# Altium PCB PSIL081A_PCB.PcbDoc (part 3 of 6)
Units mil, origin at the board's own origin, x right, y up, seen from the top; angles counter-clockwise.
Board outline 14000 x 8000 mil, 10 copper layers (Top Layer, Signal Layer 1, Signal Layer 2, Signal Layer 3, Signal Layer 4, Signal Layer 5, Signal Layer 6, Signal Layer 7, Signal Layer 8, Bottom Layer), stack 60.9 mil thick; 433 components, 510 nets, 1716 pads, 590 vias.
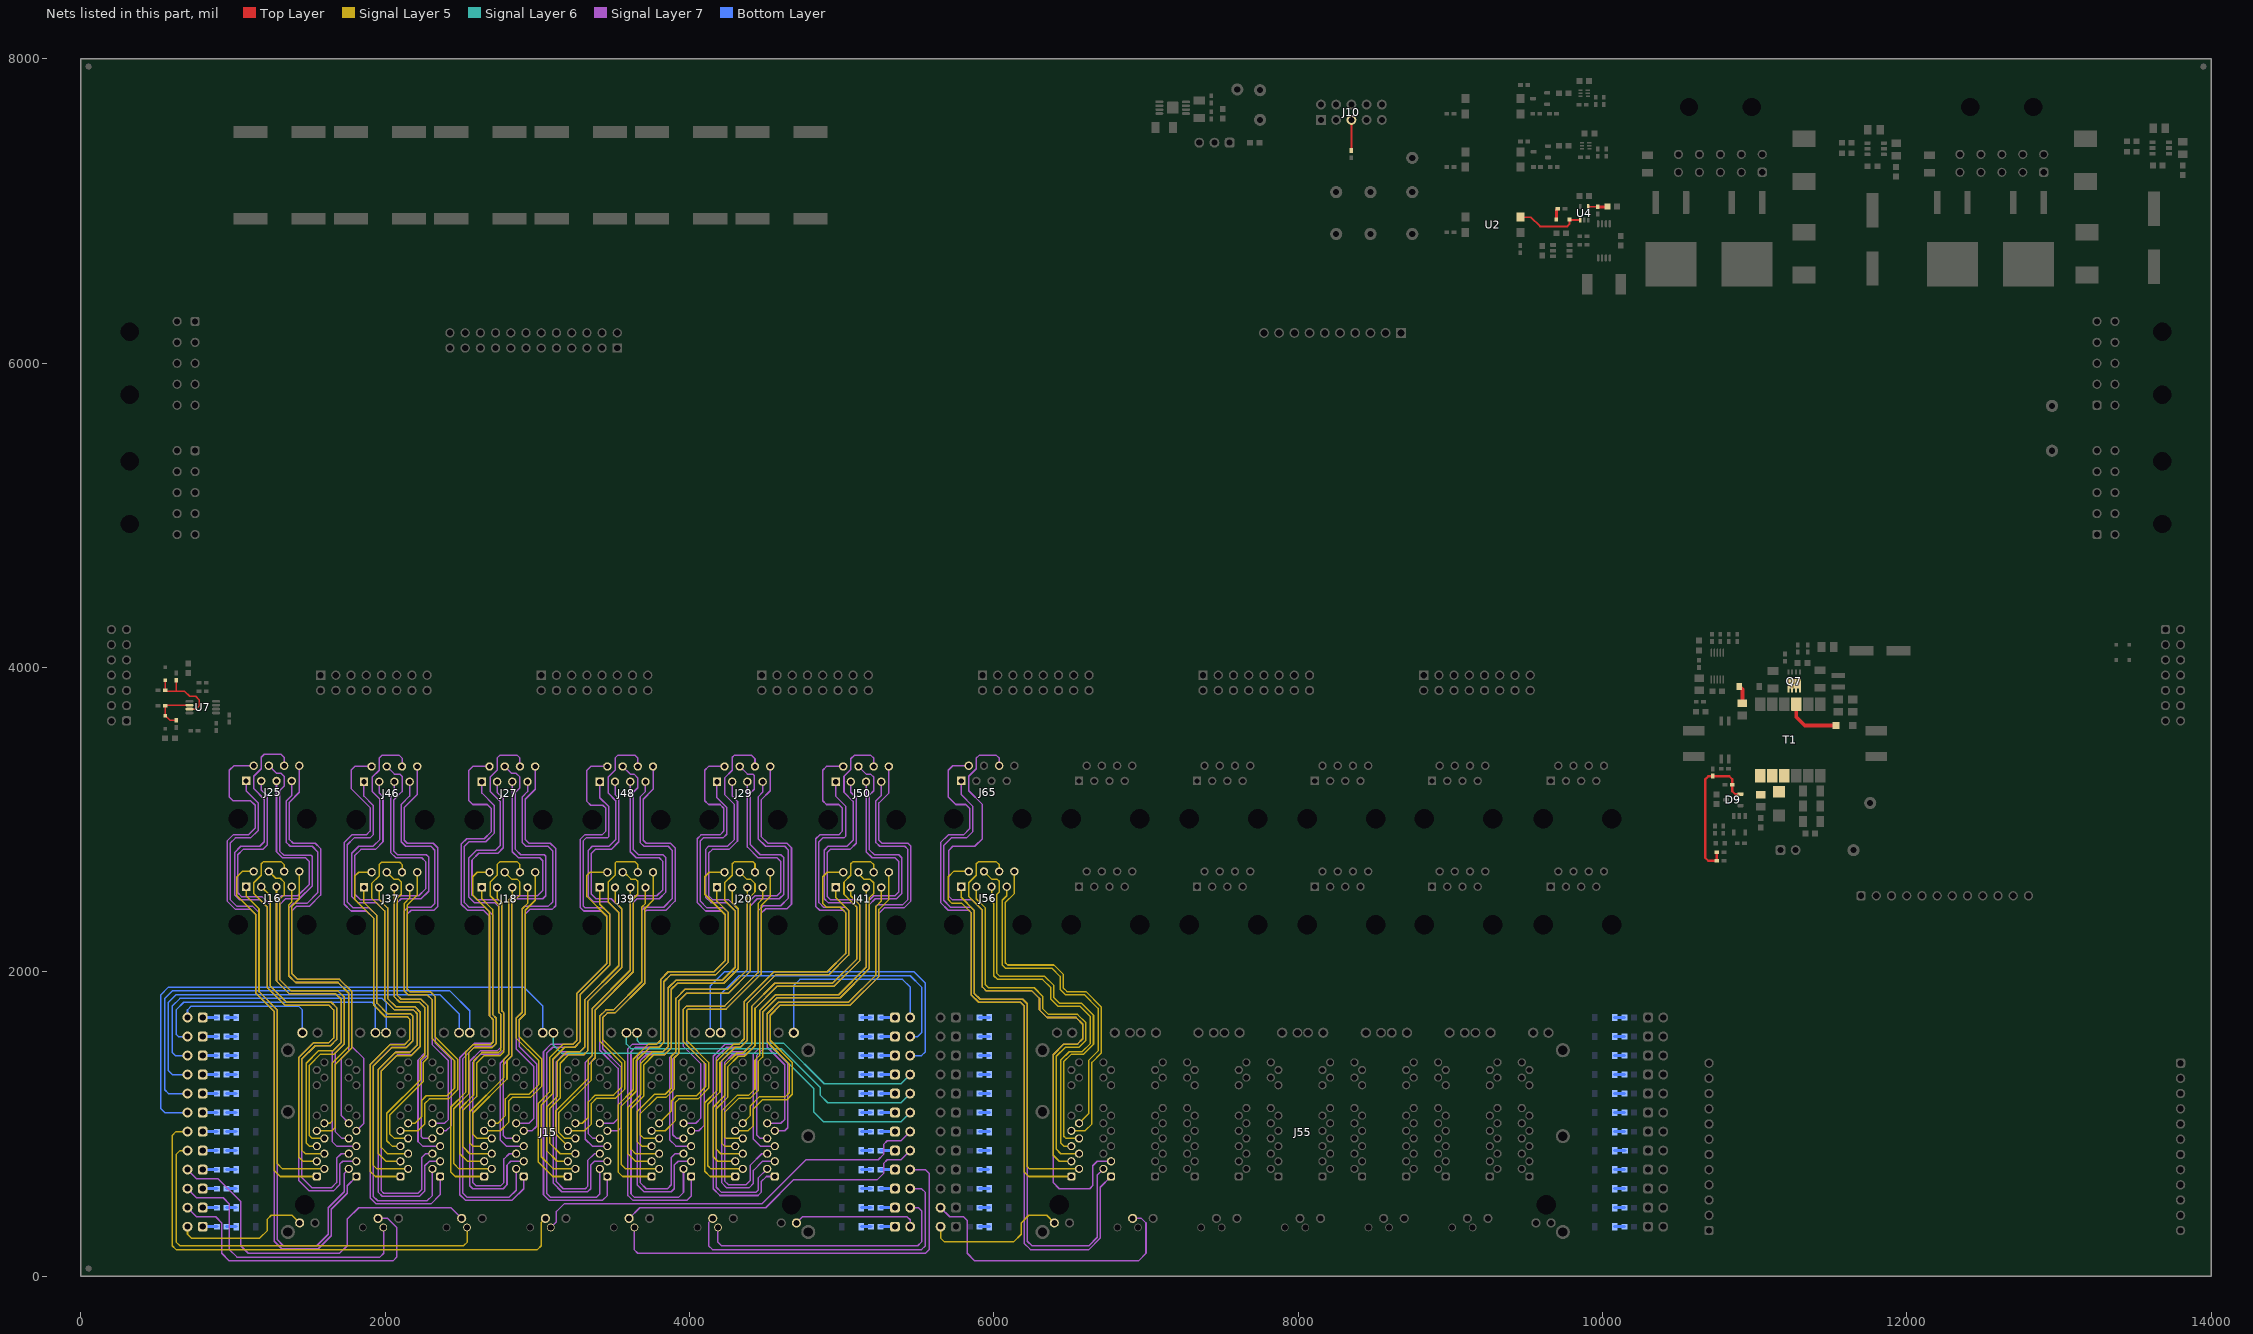
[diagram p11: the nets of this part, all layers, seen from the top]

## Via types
v1: diameter 34, hole 16, Top Layer to Bottom Layer, 429 vias
v2: diameter 26, hole 8, Top Layer to Bottom Layer, 156 vias
v3: diameter 19.68, hole 7.87, Top Layer to Bottom Layer, 5 vias

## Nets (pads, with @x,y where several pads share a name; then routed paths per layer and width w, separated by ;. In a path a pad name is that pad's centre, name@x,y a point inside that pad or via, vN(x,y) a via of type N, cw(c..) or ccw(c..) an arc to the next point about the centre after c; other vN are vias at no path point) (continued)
NetC58_2: C58.2 R18.2 U4.4 | length 128.8
  Top Layer w12: U4.4@9905.59,7029.29 9969.33,7029.29 R18.2@9970,7028.62
  Top Layer w20: R18.2@9970,7028.62 10032.13,7028.62 C58.2@10033.5,7030
NetD3_1: D3.1 U2.2 U4.1 | length 456.7
  Top Layer w12: U2.2@9461.59,6960 9530,6960 9590,6900 9770,6900 9783.31,6913.31 D3.1@9783.31,6945 9787.6,6940.71 U4.1@9854.41,6940.71
NetD3_2: D3.2 R5.2 | length 74
  Top Layer w20: D3.2@9696.69,6945 9696.69,7005.31 R5.2@9706.38,7015
NetD6_2: D6.2 R29.1 T1.7 T1.8 T1.9
NetD7_2: D7.2 Q7.5 Q7.6 Q7.7 Q7.8 Q7.9 T1.3 | length 359.7
  Top Layer w25: T1.3@11275,3759.61 T1.3@11274.37,3760.24 11274.37,3675.63 11330,3620 D7.2@11525.53,3620
NetD8_2: D8.2 R33.2 | length 118.1
  Top Layer w25: D8.2@10900.53,3875 10920,3855.53 R33.2@10920,3765
NetD9_2: D9.2 R39.1 R41.1 R42.1 R43.1 | length 991.9
  Top Layer w15: R43.1@10751.38,2785 R39.1@10751.38,2730 10695,2730 10675,2750 10675,3265 10696.38,3286.38 R41.1@10725,3286.38 10833.62,3286.38 10853.62,3266.38 R42.1@10853.62,3230 10853.62,3186.38 10872.6,3167.4 D9.2@10907.24,3167.4
NetD10_2: D10.2 R49.1 | length 64
  Bottom Layer w20: R49.1@955.96,325 D10.2@1020,325
NetD11_2: D11.2 R50.1 | length 64
  Bottom Layer w20: R50.1@955.96,825 D11.2@1020,825
NetD12_2: D12.2 R51.1 | length 64
  Bottom Layer w20: D12.2@5129.47,700 R51.1@5193.5,700
NetD13_2: D13.2 R52.2 | length 64
  Bottom Layer w20: R52.2@955.96,450 D13.2@1020,450
NetD14_2: D14.2 R53.2 | length 64
  Bottom Layer w20: R53.2@955.96,950 D14.2@1020,950
NetD15_2: D15.2 R54.2 | length 64
  Bottom Layer w20: D15.2@5129.47,575 R54.2@5193.5,575
NetD16_2: D16.2 R55.1 | length 64
  Bottom Layer w20: R55.1@955.96,1700 D16.2@1020,1700
NetD17_2: D17.2 R56.1 | length 64
  Bottom Layer w20: R56.1@955.96,1200 D17.2@1020,1200
NetD18_2: D18.2 R57.1 | length 64
  Bottom Layer w20: D18.2@5129.47,1325 R57.1@5193.5,1325
NetD19_2: D19.2 R58.2 | length 64
  Bottom Layer w20: R58.2@955.96,1575 D19.2@1020,1575
NetD20_2: D20.2 R59.2 | length 64
  Bottom Layer w20: R59.2@955.96,1075 D20.2@1020,1075
NetD21_2: D21.2 R60.2 | length 64
  Bottom Layer w20: D21.2@5129.47,1450 R60.2@5193.5,1450
NetD22_2: D22.2 R61.1 | length 64
  Bottom Layer w20: R61.1@955.96,575 D22.2@1020,575
NetD23_2: D23.2 R62.1 | length 64
  Bottom Layer w20: D23.2@5129.47,950 R62.1@5193.5,950
NetD24_2: D24.2 R63.1 | length 64
  Bottom Layer w20: D24.2@5129.47,450 R63.1@5193.5,450
NetD25_2: D25.2 R64.2 | length 64
  Bottom Layer w20: R64.2@955.96,700 D25.2@1020,700
NetD26_2: D26.2 R65.2 | length 64
  Bottom Layer w20: D26.2@5129.47,825 R65.2@5193.5,825
NetD27_2: D27.2 R66.2 | length 64
  Bottom Layer w20: D27.2@5129.47,325 R66.2@5193.5,325
NetD28_2: D28.2 R67.1 | length 64
  Bottom Layer w20: R67.1@955.96,1450 D28.2@1020,1450
NetD29_2: D29.2 R68.1 | length 64
  Bottom Layer w20: D29.2@5129.47,1075 R68.1@5193.5,1075
NetD30_2: D30.2 R69.1 | length 64
  Bottom Layer w20: D30.2@5129.47,1575 R69.1@5193.5,1575
NetD31_2: D31.2 R70.2 | length 64
  Bottom Layer w20: R70.2@955.96,1325 D31.2@1020,1325
NetD32_2: D32.2 R71.2 | length 64
  Bottom Layer w20: D32.2@5129.47,1200 R71.2@5193.5,1200
NetD33_2: D33.2 R72.2 | length 64
  Bottom Layer w20: D33.2@5129.47,1700 R72.2@5193.5,1700
NetD34_2: D34.2 R73.1 | length 64
  Bottom Layer w20: R73.1@5906.5,325 D34.2@5970.53,325
NetD35_2: D35.2 R74.1 | length 64
  Bottom Layer w20: R74.1@5906.5,825 D35.2@5970.53,825
NetD36_2: D36.2 R75.1 | length 64
  Bottom Layer w20: D36.2@10079.47,700 R75.1@10143.5,700
NetD37_2: D37.2 R76.2 | length 64
  Bottom Layer w20: R76.2@5906.5,450 D37.2@5970.53,450
NetD38_2: D38.2 R77.2 | length 64
  Bottom Layer w20: R77.2@5906.5,950 D38.2@5970.53,950
NetD39_2: D39.2 R78.2 | length 64
  Bottom Layer w20: D39.2@10079.47,575 R78.2@10143.5,575
NetD40_2: D40.2 R79.1 | length 64
  Bottom Layer w20: R79.1@5906.5,1700 D40.2@5970.53,1700
NetD41_2: D41.2 R80.1 | length 64
  Bottom Layer w20: R80.1@5906.5,1200 D41.2@5970.53,1200
NetD42_2: D42.2 R81.1 | length 64
  Bottom Layer w20: D42.2@10079.47,1325 R81.1@10143.5,1325
NetD43_2: D43.2 R82.2 | length 64
  Bottom Layer w20: R82.2@5906.5,1575 D43.2@5970.53,1575
NetD44_2: D44.2 R83.2 | length 64
  Bottom Layer w20: R83.2@5906.5,1075 D44.2@5970.53,1075
NetD45_2: D45.2 R84.2 | length 64
  Bottom Layer w20: D45.2@10079.47,1450 R84.2@10143.5,1450
NetD46_2: D46.2 R85.1 | length 64
  Bottom Layer w20: R85.1@5906.5,575 D46.2@5970.53,575
NetD47_2: D47.2 R86.1 | length 64
  Bottom Layer w20: D47.2@10079.47,950 R86.1@10143.5,950
NetD48_2: D48.2 R87.1 | length 64
  Bottom Layer w20: D48.2@10079.47,450 R87.1@10143.5,450
NetD49_2: D49.2 R88.2 | length 59
  Bottom Layer w20: R88.2@5906.5,700 D49.2@5965.53,700
NetD50_2: D50.2 R89.2 | length 69
  Bottom Layer w20: D50.2@10079.47,825 R89.2@10148.5,825
NetD51_2: D51.2 R90.2 | length 64
  Bottom Layer w20: D51.2@10079.47,325 R90.2@10143.5,325
NetD52_2: D52.2 R91.1 | length 64
  Bottom Layer w20: R91.1@5906.5,1450 D52.2@5970.53,1450
NetD53_2: D53.2 R92.1 | length 64
  Bottom Layer w20: D53.2@10079.47,1075 R92.1@10143.5,1075
NetD54_2: D54.2 R93.1 | length 64
  Bottom Layer w20: D54.2@10079.47,1575 R93.1@10143.5,1575
NetD55_2: D55.2 R94.2 | length 64
  Bottom Layer w20: R94.2@5906.5,1325 D55.2@5970.53,1325
NetD56_2: D56.2 R95.2 | length 64
  Bottom Layer w20: D56.2@10079.47,1200 R95.2@10143.5,1200
NetD57_2: D57.2 R96.2 | length 64
  Bottom Layer w20: D57.2@10079.47,1700 R96.2@10143.5,1700
NetD58_1: D58.1 R9.2 R17.2 U7.3 | length 501
  Top Layer w10: D58.1@555,3916.69 553.62,3915.32 R17.2@553.62,3850 558.62,3845 625,3845 ; R9.2@625,3916.38 625,3845 ; U7.3@712.4,3727.2 757.2,3727.2 776.38,3746.38 776.38,3788.62 754.13,3810.87 715,3810.87 680.87,3845 625,3845
NetD59_1: D59.1 R10.2 R16.2 U7.2 | length 309.5
  Top Layer w10: R10.2@625,3653.62 584.68,3653.62 D59.1@555,3683.31 553.62,3684.68 R16.2@553.62,3750 556.42,3752.8 U7.2@712.4,3752.8
NetJ10_5: J10.5 R97.2 | length 201.4
  Top Layer w15: R97.2@8350,7398.62 J10.5@8350,7600
NetJ15_A1: J15.A1 J16.2 | length 2452.5
  Signal Layer 5 w10: J16.2@1135,2660 1060,2660 1025,2625 1025,2500 1150,2375 1150,1860 1270,1740 1270,695 1310.04,654.96 J15.A1@1549.92,654.96 J15.A1@1549.92,654.96
NetJ15_A2: J15.A2 J16.1 | length 2229.4
  Signal Layer 5 w10: J16.1@1085,2560 1085,2500 1170,2415 1170,1870 1290,1750 1290,740 1325.04,704.96 J15.A2@1599.92,704.96 J15.A2@1599.92,704.96
NetJ15_A3: J15.A3 J16.6 | length 2828.8
  Signal Layer 5 w10: J16.6@1335,2660 1335,2705 1315,2725 1200,2725 1185,2710 1185,2635 1135,2585 1135,2515 1225,2425 1225,1895 1340,1780 1630,1780 1660,1750 1660,1565 1630,1535 1530,1535 1430,1435 1430,785 1460.04,754.96 J15.A3@1549.92,754.96 J15.A3@1549.92,754.96
NetJ15_A4: J15.A4 J16.3 | length 2422
  Signal Layer 5 w10: J16.3@1185,2560 1245,2500 1245,1905 1350,1800 1645,1800 1680,1765 1680,1555 1640,1515 1540,1515 1450,1425 1450,830 1475.04,804.96 J15.A4@1599.92,804.96 J15.A4@1599.92,804.96
NetJ15_A5: J15.A5 J16.5 | length 2268.8
  Signal Layer 5 w10: J16.5@1285,2560 1285,1940 1370,1855 1675,1855 1710,1820 1710,1535 1655,1480 1560,1480 1480,1400 1480,875 1500,855 J15.A5@1549.92,854.96 J15.A5@1549.92,854.96
NetJ15_A6: J15.A6 J16.4 | length 2420.3
  Signal Layer 5 w10: J16.4@1235,2660 1280,2615 1310,2615 1335,2590 1335,2505 1305,2475 1305,1950 1380,1875 1690,1875 1730,1835 1730,1525 1665,1460 1575,1460 1500,1385 1500,925 1520,905 J15.A6@1599.92,904.96 J15.A6@1599.92,904.96
NetJ15_A7: J15.A7 J16.8 | length 2204.4
  Signal Layer 5 w10: J16.8@1435,2660 1435,2480 1385,2430 1385,1990 1425,1950 1700,1950 1780,1870 1780,1500 1670,1390 1670,975 1649.96,954.96 J15.A7@1549.92,954.96
NetJ15_A8: J15.A8 J16.7 | length 1977.8
  Signal Layer 5 w10: J16.7@1385,2560 1385,2460 1365,2440 1365,1975 1410,1930 1690,1930 1760,1860 1760,1510 1650,1400 1650,1020 1634.96,1004.96 J15.A8@1599.92,1004.96 J15.A8@1599.96,1005
NetJ15_A15: J15.A15 J17.2 | length 924.5
  Signal Layer 5 w10: J17.2@700,325 700,275 725,250 1175,250 1225,300 1225,375 1250,400 1387.17,400 J15.A15@1437.32,349.84
NetJ15_A18: J15.A18 J22.2 | length 1990.2
  Signal Layer 7 w10: J22.2@700,450 760,390 885,390 925,350 925,150 975,100 2050,100 2075,125 2075,320 2015,380 2014.76,379.76 J15.A18@1952.28,379.76
NetJ15_B1: J15.B1 J25.2 | length 4616.7
  Signal Layer 7 w10: J25.2@1135,3355 1005,3355 975,3325 975,3150 1000,3125 1115,3125 1145,3095 1145,2945 1100,2900 1000,2900 960,2860 960,2465 1015,2410 1115,2410 1150,2375 1150,1860 1270,1740 1270,230 1320,180 1560,180 1645,265 1645,440 1750,545 1750,594.8 J15.B1@1810.16,654.96 J15.B1@1810.12,655
NetJ15_B2: J15.B2 J25.1 | length 4241.8
  Signal Layer 7 w10: J25.1@1085,3255 1085,3190 1165,3110 1165,2930 1115,2880 1015,2880 980,2845 980,2475 1025,2430 1130,2430 1170,2390 1170,1870 1290,1750 1290,240 1330,200 1550,200 1625,275 1625,450 1730,555 1730,674.8 J15.B2@1760.16,704.96
NetJ15_B3: J15.B3 J25.6 | length 4446.4
  Signal Layer 7 w10: J25.6@1335,3355 1335,3410 1315,3430 1205,3430 1185,3410 1185,3335 1135,3285 1135,3205 1205,3135 1205,2855 1175,2825 1050,2825 1010,2785 1010,2505 1040,2475 1175,2475 1225,2425 1225,1895 1340,1780 1630,1780 1660,1750 1660,1565 1630,1535 1530,1535 1430,1435 1430,630 1500,560 1660,560 1700,600 1700,735 1719.96,754.96 J15.B3@1810.16,754.96 J15.B3@1810.12,755
NetJ15_B4: J15.B4 J25.3 | length 3979.6
  Signal Layer 7 w10: J25.3@1185,3255 1185,3195 1225,3155 1225,2835 1195,2805 1065,2805 1030,2770 1030,2520 1055,2495 1190,2495 1245,2440 1245,1905 1350,1800 1645,1800 1680,1765 1680,1555 1640,1515 1540,1515 1450,1425 1450,650 1520,580 1645,580 1680,615 1680,775 1710,805 1760.12,805 J15.B4@1760.16,804.96
NetJ15_B5: J15.B5 J25.5 | length 3249.6
  Signal Layer 7 w10: J25.5@1285,3255 1285,2790 1325,2750 1475,2750 1500,2725 1500,2575 1425,2500 1320,2500 1285,2465 1285,1940 1370,1855 1675,1855 1710,1820 1710,1535 1650,1475 1650,885 1680.04,854.96 J15.B5@1810.16,854.96
NetJ15_B6: J15.B6 J25.4 | length 3303.7
  Signal Layer 7 w10: J25.4@1235,3355 1285,3305 1315,3305 1335,3285 1335,3220 1305.14,3190.14 1305.14,2795.14 1332.4,2767.87 1512.13,2767.87 1520,2760 1520,2565 1435,2480 1345,2480 1305,2440 1305,1950 1380,1875 1690,1875 1730,1835 1730,1525 1670,1465 1670,950 1715.04,904.96 J15.B6@1760.16,904.96
NetJ15_B7: J15.B7 J25.8 | length 3103.8
  Signal Layer 7 w10: J25.8@1435,3355 1435,3180 1370,3115 1370,2870 1395,2845 1540,2845 1575,2810 1575,2505 1500,2430 1415,2430 1385,2400 1385,1990 1425,1950 1700,1950 1780,1870 1780,1510 1860,1430 1860,1004.8 J15.B7@1810.16,954.96
NetJ15_B8: J15.B8 J25.7 | length 2934.9
  Signal Layer 7 w10: J25.7@1385,3255 1385,3160 1350,3125 1350,2850 1375,2825 1520,2825 1555,2790 1555,2520 1485,2450 1395,2450 1365,2420 1365,1975 1410,1930 1690,1930 1760,1860 1760,1480 1710,1430 1710,1055.12 J15.B8@1760.16,1004.96
NetJ15_B15: J15.B15 J26.2 | length 975.9
  Bottom Layer w10: J26.2@700,1700 700,1750 725,1775 1430,1775 1455.04,1749.96 J15.B15@1455.04,1599.84
NetJ15_B18: J15.B18 J31.2 | length 1760.4
  Bottom Layer w10: J31.2@700,1575 640,1575 625,1590 625,1750 675,1800 1915,1800 1935,1780 J15.B18@1934.96,1599.84 J15.B18@1934.96,1599.84
NetJ15_C1: J15.C1 J37.2 | length 2672.2
  Signal Layer 5 w10: J37.2@1910,2655 1825,2655 1800,2630 1800,2475 1925,2350 1925,1780 2000,1705 2145,1705 2160,1690 2160,1555 2125,1520 2030,1520 1900,1390 1900,690 1935,655 J15.C1@2099.92,654.96 J15.C1@2099.92,654.96
NetJ15_C2: J15.C2 J37.1 | length 2449.1
  Signal Layer 5 w10: J37.1@1860,2555 1860,2455 1945,2370 1945,1795 2015,1725 2165,1725 2180,1710 2180,1545 2135,1500 2040,1500 1920,1380 1920,730 1945,705 J15.C2@2149.92,704.96 J15.C2@2149.92,704.96
NetJ15_C3: J15.C3 J37.6 | length 2657.5
  Signal Layer 5 w10: J15.C3@2099.92,754.96 J15.C3@2099.92,754.96 2005,755 1955,805 1955,1360 2065,1470 2160,1470 2210,1520 2210,1725 2185,1750 2060,1750 1995,1815 1995,2400 1910,2485 1910,2580 1960,2630 1960,2705 1975,2720 2095,2720 2110,2705 J37.6@2110,2655
NetJ15_C4: J15.C4 J37.3 | length 2247.8
  Signal Layer 5 w10: J37.3@1960,2555 1960,2475 2015,2420 2015,1825 2070,1770 2195,1770 2230,1735 2230,1510 2170,1450 2075,1450 1975,1350 1975,845 2015,805 J15.C4@2149.92,804.96 J15.C4@2149.92,804.96
NetJ15_C5: J15.C5 J37.5 | length 2032
  Signal Layer 5 w10: J37.5@2060,2555 2060,1835 2095,1800 2225,1800 2260,1765 2260,1450 2230,1420 2230,1290 2010,1070 2010,890 2045,855 J15.C5@2099.92,854.96 J15.C5@2099.92,854.96
NetJ15_C6: J15.C6 J37.4 | length 2182.2
  Signal Layer 5 w10: J37.4@2010,2655 2055,2610 2085,2610 2105,2590 2105,2510 2080,2485 2080,1845 2105,1820 2235,1820 2280,1775 2280,1435 2250,1405 2250,1280 2030,1060 2030,935 2060,905 J15.C6@2149.92,904.96 J15.C6@2149.92,904.96
NetJ15_C7: J15.C7 J37.8 | length 2238.7
  Signal Layer 5 w10: J15.C7@2099.92,954.96 2099.96,955 2215,955 2260,1000 2260,1135 2290,1165 2415,1165 2475,1225 2475,1425 2330,1570 2330,1835 2295,1870 2160,1870 2145,1885 2145,2440 2210,2505 J37.8@2210,2655
NetJ15_C8: J15.C8 J37.7 | length 2006.3
  Signal Layer 5 w10: J15.C8@2149.92,1004.96 2194.96,1004.96 2240,1050 2240,1155 2270,1185 2405,1185 2455,1235 2455,1415 2310,1560 2310,1815 2275,1850 2150,1850 2125,1875 2125,2450 2160,2485 J37.7@2160,2555
NetJ15_C15: J15.C15 J38.2 | length 1833.5
  Signal Layer 7 w10: J38.2@700,575 760,515 935,515 975,475 975,175 1025,125 1965,125 1990,150 1990,317.24 J15.C15@1987.32,319.92
NetJ15_C18: J15.C18 J43.2 | length 2455.8
  Signal Layer 7 w10: J43.2@700,700 760,640 900,640 1050,490 1050,200 1100,150 1700,150 1750,200 1750,375 1825,450 2432.05,450 J15.C18@2502.28,379.76
NetJ15_D1: J15.D1 J46.2 | length 4239.6
  Signal Layer 7 w10: J46.2@1910,3350 1800,3350 1775,3325 1775,3205 1900,3080 1900,2925 1875,2900 1780,2900 1730,2850 1730,2445 1775,2400 1875,2400 1925,2350 1925,1780 2000,1705 2145,1705 2160,1690 2160,1555 2130,1525 2035,1525 1900,1390 1900,515 1940,475 2300,475 2360.16,535.16 J15.D1@2360.16,654.96
NetJ15_D2: J15.D2 J46.1 | length 3964.6
  Signal Layer 7 w10: J46.1@1860,3250 1860,3155 1920,3095 1920,2900 1900,2880 1795,2880 1750,2835 1750,2460 1790,2420 1895,2420 1945,2370 1945,1795 2015,1725 2165,1725 2180,1710 2180,1545 2140,1505 2045,1505 1920,1380 1920,525 1950,495 2275,495 2310.16,530.16 J15.D2@2310.16,704.96
NetJ15_D3: J15.D3 J46.6 | length 4338.5
  Signal Layer 7 w10: J46.6@2110,3350 2110,3405 2090,3425 1980,3425 1960,3405 1960,3325 1915,3280 1915,3185 1965,3135 1965,2870 1920,2825 1825,2825 1780,2780 1780,2495 1820,2455 1940,2455 1995,2400 1995,1815 2060,1750 2185,1750 2210,1725 2210,1520 2165,1475 2070,1475 1955,1360 1955,550 1980,525 2225,525 2260,560 2260,725 2289.96,754.96 J15.D3@2360.16,754.96
NetJ15_D4: J15.D4 J46.3 | length 3890.5
  Signal Layer 7 w10: J46.3@1960,3250 1960,3175 1985,3150 1985,2855 1935,2805 1840,2805 1800,2765 1800,2510 1835,2475 1960,2475 2015,2420 2015,1825 2070,1770 2195,1770 2230,1735 2230,1510 2175,1455 2080,1455 1975,1350 1975,560 1990,545 2215,545 2240,570 2240,780 2264.96,804.96 J15.D4@2310.16,804.96
NetJ15_D5: J15.D5 J46.5 | length 3069.4
  Signal Layer 7 w10: J46.5@2060,3250 2060,3175 2035,3150 2035,2785 2070,2750 2240,2750 2265,2725 2265,2545 2220,2500 2085,2500 2060,2475 2060,1835 2095,1800 2225,1800 2260,1765 2260,1465 2215,1420 2215,885 2245,855 2360.12,855 J15.D5@2360.16,854.96
NetJ15_D6: J15.D6 J46.4 | length 3141.4
  Signal Layer 7 w10: J46.4@2010,3350 2060,3300 2095,3300 2110,3285 2110,3185 2055,3130 2055,2795 2080,2770 2270,2770 2285,2755 2285,2530 2235,2480 2105,2480 2080,2455 2080,1845 2105,1820 2235,1820 2280,1775 2280,1455 2235,1410 2235,920 2250.04,904.96 J15.D6@2310.16,904.96
NetJ15_D7: J15.D7 J46.8 | length 3045.2
  Signal Layer 7 w10: J46.8@2210,3350 2210,3165 2125,3080 2125,2865 2145,2845 2315,2845 2345,2815 2345,2430 2320,2405 2170,2405 2145,2380 2145,1885 2160,1870 2295,1870 2330,1835 2330,1530 2435,1425 2435,990 2399.96,954.96 J15.D7@2360.16,954.96
NetJ15_D8: J15.D8 J46.7 | length 2909.8
  Signal Layer 7 w10: J46.7@2160,3250 2160,3155 2105,3100 2105,2855 2135,2825 2300,2825 2325,2800 2325,2450 2300,2425 2150,2425 2125,2400 2125,1875 2150,1850 2275,1850 2310,1815 2310,1520 2415,1415 2415,1030 2389.96,1004.96 J15.D8@2310.16,1004.96
NetJ15_D15: J15.D15 J47.2 | length 2049.5
  Bottom Layer w10: J47.2@700,1450 620,1450 600,1470 600,1775 650,1825 1980,1825 2005.04,1799.96 J15.D15@2005.04,1599.84
NetJ15_D18: J15.D18 J52.2 | length 2693
  Bottom Layer w10: J52.2@700,1325 600,1325 575,1350 575,1800 625,1850 2360,1850 2485,1725 J15.D18@2484.96,1599.84 J15.D18@2484.96,1599.84
NetJ15_E1: J15.E1 J18.2 | length 2534.1
  Signal Layer 5 w10: J15.E1@2649.92,654.96 J15.E1@2649.92,654.96 2460,655 2430,685 2430,1110 2530,1210 2530,1475 2575,1520 2690,1520 2710,1540 2710,1685 2685,1710 2685,2395 2575,2505 2575,2625 2605,2655 J18.2@2685,2655
NetJ15_E2: J15.E2 J18.1 | length 2304.9
  Signal Layer 5 w10: J18.1@2635,2555 2635,2480 2705,2410 2705,1720 2730,1695 2730,1530 2700,1500 2580.28,1500 2550,1469.72 2550,1200 2450,1100 2450,740 2485,705 J15.E2@2699.92,704.96 J15.E2@2699.92,704.96
NetJ15_E3: J15.E3 J18.6 | length 2521.1
  Signal Layer 5 w10: J15.E3@2649.92,754.96 J15.E3@2649.92,754.96 2540,755 2490,805 2490,1100 2580,1190 2580,1415 2635,1470 2745,1470 2760,1485 2760,1720 2745,1735 2745,2445 2690,2500 2690,2590 2735,2635 2735,2705 2755,2725 2865,2725 2885,2705 J18.6@2885,2655
NetJ15_E4: J15.E4 J18.3 | length 2105.6
  Signal Layer 5 w10: J15.E4@2699.92,804.96 2555.04,804.96 2510,850 2510,1090 2600,1180 2600,1400 2650,1450 2755,1450 2780,1475 2780,1730 2765,1745 2765,2455 2735,2485 J18.3@2735,2555
NetJ15_E5: J15.E5 J18.5 | length 1899.2
  Signal Layer 5 w10: J15.E5@2649.92,854.96 J15.E5@2649.92,854.96 2575,855 2555,875 2555,1080 2780,1305 2780,1425 2810,1455 2810,2470 2835,2495 J18.5@2835,2555
NetJ15_E6: J15.E6 J18.4 | length 2047.7
  Signal Layer 5 w10: J15.E6@2699.92,904.96 J15.E6@2699.92,904.96 2605,905 2575,935 2575,1070 2800,1295 2800,1415 2830,1445 2830,2450 2885,2505 2885,2590 2865,2610 2830,2610 J18.4@2785,2655
NetJ15_E7: J15.E7 J18.8 | length 2094.9
  Signal Layer 5 w10: J15.E7@2649.92,954.96 2754.96,954.96 2810,1010 2810,1150 2835,1175 2955,1175 3030,1250 3030,1425 2880,1575 2880,1685 2920,1725 2920,2405 2985,2470 J18.8@2985,2655
NetJ15_E8: J15.E8 J18.7 | length 1868.4
  Signal Layer 5 w10: J15.E8@2699.92,1004.96 2739.96,1004.96 2790,1055 2790,1165 2820,1195 2945,1195 3010,1260 3010,1415 2860,1565 2860,1695 2900,1735 2900,2415 2935,2450 J18.7@2935,2555
NetJ15_E15: J15.E15 J19.2 | length 2692.1
  Signal Layer 5 w10: J19.2@700,825 650,825 625,800 625,225 650,200 2515,200 2540,225 2540,317.24 J15.E15@2537.32,319.92
NetJ15_E18: J15.E18 J23.2 | length 3472.1
  Signal Layer 5 w10: J23.2@700,950 625,950 600,925 600,200 625,175 3000,175 3025,200 3025,352.48 J15.E18@3052.28,379.76
NetJ15_F1: J15.F1 J27.2 | length 4051.8
  Signal Layer 7 w10: J27.2@2685,3350 2575,3350 2550,3325 2550,3125 2575,3100 2670,3100 2695,3075 2695,2920 2650,2875 2535,2875 2500,2840 2500,2445 2540,2405 2645,2405 2685,2365 2685,1710 2710,1685 2710,1540 2700,1530 2585,1530 2490,1435 2490,535 2525,500 2835,500 2910,575 2910,654.8 J15.F1@2910.16,654.96
NetJ15_F2: J15.F2 J27.1 | length 3712.1
  Signal Layer 7 w10: J27.1@2635,3250 2635,3175 2715,3095 2715,2910 2660,2855 2550,2855 2520,2825 2520,2455 2550,2425 2655,2425 2705,2375 2705,1720 2730,1695 2730,1530 2710,1510 2590.28,1510 2510,1429.72 2510,545 2535,520 2815,520 2860.16,565.16 J15.F2@2860.16,704.96
NetJ15_F3: J15.F3 J27.6 | length 4065.5
  Signal Layer 7 w10: J27.6@2885,3350 2885,3405 2865,3425 2755,3425 2735,3405 2735,3325 2690,3280 2690,3185 2755,3120 2755,2830 2725,2800 2600,2800 2550,2750 2550,2490 2585,2455 2720,2455 2745,2430 2745,1735 2760,1720 2760,1505 2735,1480 2623.46,1480 2555.26,1411.8 2555.26,594.74 2575,575 2775,575 2800,600 2800,730 2825,755 2910.12,755 J15.F3@2910.16,754.96
NetJ15_F4: J15.F4 J27.3 | length 3608
  Signal Layer 7 w10: J27.3@2735,3250 2735,3180 2775,3140 2775,2815 2740,2780 2615,2780 2570,2735 2570,2505 2600,2475 2745,2475 2765,2455 2765,1745 2780,1730 2780,1490 2750,1460 2630,1460 2575,1405 2575,615 2595,595 2760,595 2780,615 2780,770 2814.96,804.96 J15.F4@2860.16,804.96
NetJ15_F5: J15.F5 J27.5 | length 2901.3
  Signal Layer 7 w10: J27.5@2835,3250 2835,2790 2875,2750 3015,2750 3035,2730 3035,2535 3000,2500 2840,2500 2810,2470 2810,1455 2755,1400 2755,895 2795,855 2910.12,855 J15.F5@2910.16,854.96
NetJ15_F6: J15.F6 J27.4 | length 2982
  Signal Layer 7 w10: J27.4@2785,3350 2830,3305 2860,3305 2885,3280 2885,3210 2855,3180 2855,2805 2890,2770 3045,2770 3055,2760 3055,2500 3035,2480 2860,2480 2830,2450 2830,1445 2775,1390 2775,925 2795.04,904.96 J15.F6@2860.16,904.96
NetJ15_F7: J15.F7 J27.8 | length 2886
  Signal Layer 7 w10: J15.F7@2910.16,954.96 2964.96,954.96 2995,985 2995,1395 2880,1510 2880,1685 2920,1725 2920,2380 2950,2410 3095,2410 3120,2435 3120,2810 3085,2845 2945,2845 2920,2870 2920,3135 2985,3200 J27.8@2985,3350
NetJ15_F8: J15.F8 J27.7 | length 2762.4
  Signal Layer 7 w10: J15.F8@2860.16,1004.96 2944.96,1004.96 2975,1035 2975,1380 2860,1495 2860,1695 2900,1735 2900,2415 2915,2430 3070,2430 3100,2460 3100,2795 3070,2825 2925,2825 2900,2850 2900,3150 2935,3185 J27.7@2935,3250
NetJ15_F15: J15.F15 J28.2 | length 2985.1
  Bottom Layer w10: J28.2@700,1200 575,1200 550,1225 550,1825 600,1875 2425,1875 2555.04,1744.96 J15.F15@2555.04,1599.84
NetJ15_F18: J15.F18 J32.2 | length 3693
  Bottom Layer w10: J32.2@700,1075 550,1075 525,1100 525,1850 575,1900 2910,1900 3035,1775 J15.F18@3034.96,1599.84 J15.F18@3034.96,1599.84
NetJ15_G1: J15.G1 J39.2 | length 2540.9
  Signal Layer 5 w10: J15.G1@3199.92,654.96 J15.G1@3199.92,654.96 3100,655 3005,750 3005,1135 3080,1210 3080,1435 3170,1525 3235,1525 3260,1550 3260,1860 3455,2055 3455,2365 3325,2495 3325,2635 3345,2655 J39.2@3460,2655
NetJ15_G2: J15.G2 J39.1 | length 2279.5
  Signal Layer 5 w10: J15.G2@3249.92,704.96 J15.G2@3249.92,704.96 3105,705 3025,785 3025,1125 3100,1200 3100,1425 3180,1505 3245,1505 3280,1540 3280,1850 3475,2045 3475,2380 3410,2445 J39.1@3410,2555
NetJ15_G3: J15.G3 J39.6 | length 2565.5
  Signal Layer 5 w10: J15.G3@3199.92,754.96 J15.G3@3199.92,754.96 3130,755 3060,825 3060,1110 3130,1180 3130,1410 3195,1475 3280,1475 3310,1505 3310,1815 3535,2040 3535,2390 3465,2460 3465,2590 3510,2635 3510,2715 3520,2725 3640,2725 3660,2705 J39.6@3660,2655
NetJ15_G4: J15.G4 J39.3 | length 2152.9
  Signal Layer 5 w10: J15.G4@3249.92,804.96 J15.G4@3249.92,804.96 3150,805 3080,875 3080,1100 3150,1170 3150,1400 3205,1455 3305,1455 3330,1480 3330,1805 3555,2030 3555,2415 3510,2460 J39.3@3510,2555
NetJ15_G5: J15.G5 J39.5 | length 1936.1
  Signal Layer 5 w10: J15.G5@3199.92,854.96 3120,934.88 3120,1085 3335,1300 3335,1425 3360,1450 3360,1760 3610,2010 J39.5@3610,2555
NetJ15_G6: J15.G6 J39.4 | length 2116.7
  Signal Layer 5 w10: J15.G6@3249.92,904.96 J15.G6@3249.92,904.96 3180,905 3140,945 3140,1075 3355,1290 3355,1410 3380,1435 3380,1750 3630,2000 3630,2480 3660,2510 3660,2595 3645,2610 3615,2610 3570,2655 J39.4@3560,2655
NetJ15_G7: J15.G7 J39.8 | length 2219.1
  Signal Layer 5 w10: J15.G7@3199.92,954.96 3309.96,954.96 3355,1000 3355,1135 3390,1170 3515,1170 3575,1230 3575,1410 3430,1555 3430,1700 3460,1730 3510,1730 3705,1925 3705,2415 3760,2470 J39.8@3760,2655
NetJ15_G8: J15.G8 J39.7 | length 1986.7
  Signal Layer 5 w10: J15.G8@3249.92,1004.96 3294.96,1004.96 3335,1045 3335,1145 3380,1190 3500,1190 3555,1245 3555,1400 3410,1545 3410,1710 3450,1750 3500,1750 3685,1935 3685,2425 3710,2450 J39.7@3710,2555
NetJ15_G15: J15.G15 J40.2 | length 2701.2
  Signal Layer 7 w10: J15.G15@3087.32,319.92 3125,357.6 3125,425 3175,475 4475,475 4765,765 5240,765 5275,800 5275,865 5300,890 5390,890 J40.2@5450,950
NetJ15_G18: J15.G18 J44.2 | length 2070.2
  Signal Layer 7 w10: J15.G18@3602.28,379.76 3672.52,450 4500,450 4685,635 5235,635 5275,675 5275,740 5300,765 5390,765 J44.2@5450,825
NetJ15_H1: J15.H1 J48.2 | length 4140.4
  Signal Layer 7 w10: J48.2@3460,3350 3350,3350 3325,3325 3325,3120 3350,3095 3430,3095 3450,3075 3450,2925 3425,2900 3310,2900 3280,2870 3280,2425 3305,2400 3420,2400 3455,2365 3455,2055 3260,1860 3260,1550 3235,1525 3090,1525 3040,1475 3040,535 3075,500 3430,500 3460,530 3460,654.8 J15.H1@3460.16,654.96
NetJ15_H2: J15.H2 J48.1 | length 3815.6
  Signal Layer 7 w10: J48.1@3410,3250 3410,3145 3470,3085 3470,2890 3460,2880 3320,2880 3300,2860 3300,2435 3315,2420 3435,2420 3475,2380 3475,2045 3280,1850 3280,1540 3245,1505 3100,1505 3060,1465 3060,545 3085,520 3390,520 3410.16,540.16 J15.H2@3410.16,704.96
NetJ15_H3: J15.H3 J48.6 | length 4136.3
  Signal Layer 7 w10: J15.H3@3460.16,754.96 3460.12,755 3375,755 3350,730 3350,575 3330,555 3160,555 3105,610 3105,1425 3155,1475 3280,1475 3310,1505 3310,1815 3535,2040 3535,2390 3465,2460 3370,2460 3335,2495 3335,2800 3360,2825 3470,2825 3515,2870 3515,3125 3465,3175 3465,3280 3510,3325 3510,3405 3530,3425 3640,3425 3660,3405 J48.6@3660,3350
NetJ15_H4: J15.H4 J48.3 | length 3673.7
  Signal Layer 7 w10: J15.H4@3410.16,804.96 3374.96,804.96 3330,760 3330,590 3315,575 3170,575 3125,620 3125,1410 3170,1455 3305,1455 3330,1480 3330,1805 3555,2030 3555,2410 3485,2480 3385,2480 3355,2510 3355,2780 3380,2805 3485,2805 3535,2855 3535,3140 3510,3165 J48.3@3510,3250
NetJ15_H5: J15.H5 J48.5 | length 2986.9
  Signal Layer 7 w10: J15.H5@3460.16,854.96 3460.12,855 3360,855 3315,900 3315,1405 3360,1450 3360,1760 3610,2010 3610,2470 3640,2500 3785,2500 3825,2540 3825,2725 3800,2750 3650,2750 3610,2790 J48.5@3610,3250
NetJ15_H6: J15.H6 J48.4 | length 3050.1
  Signal Layer 7 w10: J15.H6@3410.16,904.96 3365.04,904.96 3335,935 3335,1390 3380,1435 3380,1750 3630,2000 3630,2455 3655,2480 3800,2480 3845,2525 3845,2750 3825,2770 3665,2770 3630,2805 3630,3180 3660,3210 3660,3275 3635,3300 3610,3300 J48.4@3560,3350
NetJ15_H7: J15.H7 J48.8 | length 3032.7
  Signal Layer 7 w10: J15.H7@3460.16,954.96 3529.96,954.96 3550,975 3550,1375 3430,1495 3430,1700 3460,1730 3510,1730 3705,1925 3705,2395 3715,2405 3845,2405 3905,2465 3905,2815 3875,2845 3715,2845 3695,2865 3695,3135 3760,3200 J48.8@3760,3350
NetJ15_H8: J15.H8 J48.7 | length 2891.5
  Signal Layer 7 w10: J15.H8@3410.16,1004.96 3499.96,1004.96 3530,1035 3530,1365 3410,1485 3410,1710 3450,1750 3500,1750 3685,1935 3685,2405 3705,2425 3830,2425 3885,2480 3885,2800 3860,2825 3700,2825 3675,2850 3675,3150 3710,3185 J48.7@3710,3250
NetJ15_H15: J15.H15 J49.2 | length 2752.5
  Signal Layer 6 w10: J15.H15@3105,1599.8 J15.H15@3105.04,1599.84 3105.04,1523.53 3102.6,1521.09 3158.69,1465 4585,1465 4815,1235 4815,1080 4880,1015 5390,1015 J49.2@5450,1075
NetJ15_H18: J15.H18 J53.2 | length 2154.7
  Signal Layer 6 w10: J15.H18@3584.96,1599.84 3584.96,1525.04 3615,1495 4605,1495 4857.82,1242.18 4857.82,1190 4907.82,1140 5390,1140 J53.2@5450,1200
NetJ15_I1: J15.I1 J20.2 | length 2870.7
  Signal Layer 5 w10: J15.I1@3749.92,654.96 J15.I1@3749.92,654.96 3560,655 3530,685 3530,1125 3630,1225 3630,1425 3730,1525 3785,1525 3810,1550 3810,1950 3860,2000 4160,2000 4235,2075 4235,2375 4100,2510 4100,2625 4130,2655 J20.2@4230,2655
NetJ15_I2: J15.I2 J20.1 | length 2613.4
  Signal Layer 5 w10: J15.I2@3799.92,704.96 3580.04,704.96 3550,735 3550,1115 3650,1215 3650,1415 3740,1505 3800,1505 3830,1535 3830,1935 3875,1980 4170,1980 4255,2065 4255,2390 4180,2465 J20.1@4180,2555
NetJ15_I3: J15.I3 J20.6 | length 2859.5
  Signal Layer 5 w10: J15.I3@3749.92,754.96 J15.I3@3749.92,754.96 3645,755 3595,805 3595,1110 3680,1195 3680,1400 3755,1475 3825,1475 3860,1510 3860,1895 3910,1945 4215,1945 4300,2030 4300,2400 4230,2470 4230,2585 4280,2635 4280,2710 4295,2725 4415,2725 4430,2710 J20.6@4430,2655
NetJ15_I4: J15.I4 J20.3 | length 2445.6
  Signal Layer 5 w10: J15.I4@3799.92,804.96 3645.04,804.96 3615,835 3615,1100 3700,1185 3700,1390 3765,1455 3835,1455 3880,1500 3880,1885 3920,1925 4225,1925 4320,2020 4320,2415 4280,2455 J20.3@4280,2555
NetJ15_I5: J15.I5 J20.5 | length 2282.7
  Signal Layer 5 w10: J15.I5@3749.92,854.96 J15.I5@3749.92,854.96 3685,855 3655,885 3655,1080 3770,1195 3840,1195 3880,1235 3880,1445 3910,1475 3910,1825 3970,1885 4250,1885 4380,2015 J20.5@4380,2555
NetJ15_I6: J15.I6 J20.4 | length 2425.3
  Signal Layer 5 w10: J15.I6@3799.92,904.96 3700.04,904.96 3675,930 3675,1065 3785,1175 3845,1175 3900,1230 3900,1435 3930,1465 3930,1810 3980,1860 4255,1860 4400,2005 4400,2495 4430,2525 4430,2580 4400,2610 4375,2610 J20.4@4330,2655
NetJ15_I7: J15.I7 J20.8 | length 2415.7
  Signal Layer 5 w10: J15.I7@3749.92,954.96 3839.96,954.96 3905,1020 3905,1140 3930,1165 4055,1165 4125,1235 4125,1405 3980,1550 3980,1745 3990,1755 4240,1755 4470,1985 4470,2435 4530,2495 J20.8@4530,2655
NetJ15_I8: J15.I8 J20.7 | length 2174.5
  Signal Layer 5 w10: J15.I8@3799.92,1004.96 3880,1085.04 3880,1150 3915,1185 4045,1185 4105,1245 4105,1395 3960,1540 3960,1755 3980,1775 4230,1775 4450,1995 4450,2450 4480,2480 J20.7@4480,2555
NetJ15_I15: J15.I15 J21.2 | length 2741.9
  Signal Layer 7 w10: J15.I15@3637.32,319.92 3635,317.6 3635,175 3660,150 5550,150 5575,175 5575,675 5550,700 J21.2@5450,700
NetJ15_I18: J15.I18 J24.2 | length 2097.1
  Signal Layer 7 w10: J15.I18@4152.28,379.76 4125,352.48 4125,200 4150,175 5525,175 5550,200 5550,550 5525,575 J24.2@5450,575
NetJ15_J1: J15.J1 J29.2 | length 4417
  Signal Layer 7 w10: J15.J1@4010.16,654.96 4010,654.8 4010,525 3985,500 3625,500 3595,530 3595,1494.48 3625.52,1525 3785,1525 3810,1550 3810,1950 3860,2000 4160,2000 4235,2075 4235,2375 4210,2400 4105,2400 4050,2455 4050,2875 4075,2900 4200,2900 4225,2925 4225,3075 4200,3100 4125,3100 4100,3125 4100,3325 4125,3350 J29.2@4230,3350
NetJ15_J2: J15.J2 J29.1 | length 4076.2
  Signal Layer 7 w10: J15.J2@3960.16,704.96 3960.16,550.16 3930,520 3635,520 3615,540 3615,1475 3645,1505 3800,1505 3830,1535 3830,1935 3875,1980 4170,1980 4255,2065 4255,2390 4225,2420 4115,2420 4070,2465 4070,2860 4090,2880 4220,2880 4245,2905 4245,3080 4242.87,3082.13 4242.87,3082.4 4207.4,3117.87 4207.13,3117.87 4180,3145 J29.1@4180,3250
NetJ15_J3: J15.J3 J29.6 | length 4440.8
  Signal Layer 7 w10: J15.J3@4010.16,754.96 4010.12,755 3925,755 3900,730 3900,575 3880,555 3700,555 3655,600 3655,1440 3690,1475 3825,1475 3860,1510 3860,1895 3910,1945 4215,1945 4300,2030 4300,2400 4245,2455 4140,2455 4105,2490 4105,2805 4125,2825 4250,2825 4295,2870 4295,3100 4230,3165 4230,3275 4280,3325 4280,3410 4295,3425 4405,3425 4430,3400 J29.6@4430,3350
NetJ15_J4: J15.J4 J29.3 | length 3953.5
  Signal Layer 7 w10: J15.J4@3960.16,804.96 3904.96,804.96 3880,780 3880,600 3855,575 3715,575 3675,615 3675,1415 3715,1455 3835,1455 3880,1500 3880,1885 3920,1925 4225,1925 4320,2020 4320,2410 4255,2475 4150,2475 4125,2500 4125,2780 4150,2805 4260,2805 4315,2860 4315,3120 4280,3155 J29.3@4280,3250
NetJ15_J5: J15.J5 J29.5 | length 3227.4
  Signal Layer 7 w10: J15.J5@4010.16,854.96 4010.12,855 3910,855 3870,895 3870,1435 3910,1475 3910,1825 3970,1885 4250,1885 4380,2015 4380,2450 4430,2500 4575,2500 4600,2525 4600,2725 4575,2750 4450,2750 4380,2820 J29.5@4380,3250
NetJ15_J6: J15.J6 J29.4 | length 3289.4
  Signal Layer 7 w10: J15.J6@3960.16,904.96 3915.04,904.96 3890,930 3890,1425 3930,1465 3930,1810 3980,1860 4255,1860 4400,2005 4400,2435 4445,2480 4590,2480 4620,2510 4620,2750 4600,2770 4465,2770 4400,2835 4400,3175 4425,3200 4425,3290 4415,3300 4380,3300 J29.4@4330,3350
NetJ15_J7: J15.J7 J29.8 | length 3202.2
  Signal Layer 7 w10: J15.J7@4010.16,954.96 4059.96,954.96 4095,990 4095,1405 3980,1520 3980,1745 3990,1755 4240,1755 4470,1985 4470,2385 4500,2415 4640,2415 4670,2445 4670,2815 4640,2845 4515,2845 4470,2890 4470,3130 4530,3190 J29.8@4530,3350
NetJ15_J8: J15.J8 J29.7 | length 3055.1
  Signal Layer 7 w10: J15.J8@3960.16,1004.96 4039.96,1004.96 4075,1040 4075,1395 3960,1510 3960,1755 3980,1775 4230,1775 4450,1995 4450,2400 4485,2435 4600,2435 4650,2485 4650,2800 4625,2825 4500,2825 4450,2875 4450,3150 4480,3180 J29.7@4480,3250
NetJ15_J15: J15.J15 J30.2 | length 1987.8
  Signal Layer 6 w10: J15.J15@3655.04,1599.84 3655,1599.8 3655,1550 3675,1530 4620,1530 4885,1265 5390,1265 J30.2@5450,1325
NetJ15_J18: J15.J18 J33.2 | length 2351
  Top Layer w10: J15.J18@4134.96,1599.84 J15.J18@4134.96,1599.84
  Bottom Layer w10: J15.J18@4134.96,1599.84 J15.J18@4134.96,1599.84 4135,1905 4230,2000 5475,2000 5550,1925 5550,1475 5525,1450 J33.2@5450,1450
NetJ15_K1: J15.K1 J41.2 | length 3020.4
  Signal Layer 5 w10: J15.K1@4299.92,654.96 J15.K1@4299.92,654.96 4135,655 4100,690 4100,1140 4180,1220 4180,1415 4290,1525 4325,1525 4360,1560 4360,1805 4555,2000 4905,2000 5025,2120 5025,2390 4990,2425 4900,2425 4875,2450 4875,2625 4905,2655 J41.2@5010,2655
NetJ15_K2: J15.K2 J41.1 | length 2712.1
  Signal Layer 5 w10: J15.K2@4349.92,704.96 4140.04,704.96 4120,725 4120,1130 4200,1210 4200,1405 4300,1505 4335,1505 4380,1550 4380,1795 4565,1980 4915,1980 5045,2110 5045,2405 4960,2490 J41.1@4960,2555
NetJ15_K3: J15.K3 J41.6 | length 2988.2
  Signal Layer 5 w10: J15.K3@4299.92,754.96 J15.K3@4299.92,754.96 4185,755 4155,785 4155,1110 4230,1185 4230,1385 4310,1465 4350,1465 4410,1525 4410,1775 4560,1925 4940,1925 5100,2085 5100,2425 5015,2510 5015,2590 5060,2635 5060,2710 5075,2725 5190,2725 5210,2705 J41.6@5210,2655
NetJ15_K4: J15.K4 J41.3 | length 2566.8
  Signal Layer 5 w10: J15.K4@4349.92,804.96 4205.04,804.96 4175,835 4175,1100 4250,1175 4250,1375 4320,1445 4360,1445 4430,1515 4430,1760 4575,1905 4950,1905 5120,2075 5120,2440 5060,2500 J41.3@5060,2555
NetJ15_K5: J15.K5 J41.5 | length 2458.8
  Signal Layer 5 w10: J15.K5@4299.92,854.96 J15.K5@4299.92,854.96 4230,855 4210,875 4210,1085 4315,1190 4390,1190 4430,1230 4430,1420 4460,1450 4460,1745 4565,1850 4980,1850 5160,2030 J41.5@5160,2555
NetJ15_K6: J15.K6 J41.4 | length 2621.9
  Signal Layer 5 w10: J15.K6@4349.92,904.96 4240.04,904.96 4230,915 4230,1075 4325,1170 4400,1170 4450,1220 4450,1410 4480,1440 4480,1735 4575,1830 4990,1830 5180,2020 5180,2485 5210,2515 5210,2585 5185,2610 5145,2610 5110,2645 J41.4@5110,2655
NetJ15_K7: J15.K7 J41.8 | length 2651.6
  Signal Layer 5 w10: J15.K7@4299.92,954.96 4384.96,954.96 4420,990 4420,1100 4480,1160 4640,1160 4675,1195 4675,1405 4530,1550 4530,1715 4595,1780 5055,1780 5245,1970 5245,2410 5310,2475 J41.8@5310,2655
NetJ15_K8: J15.K8 J41.7 | length 2416.2
  Signal Layer 5 w10: J15.K8@4349.92,1004.96 4400,1055.04 4400,1120 4460,1180 4630,1180 4655,1205 4655,1395 4510,1540 4510,1725 4585,1800 5045,1800 5225,1980 5225,2430 5260,2465 J41.7@5260,2555
NetJ15_K15: J15.K15 J42.2 | length 1744.9
  Signal Layer 7 w10: J15.K15@4187.32,319.92 4185,317.6 4185,225 4210,200 5500,200 5525,225 5525,430 5505,450 J42.2@5450,450
NetJ15_K18: J15.K18 J45.2 | length 817.2
  Signal Layer 7 w10: J15.K18@4702.68,349.84 4742.83,390 5430,390 5450,370 J45.2@5450,325
NetJ15_L1: J15.L1 J50.2 | length 4448.2
  Signal Layer 7 w10: J15.L1@4560,654.8 J15.L1@4560.16,654.96 4504.96,654.96 4470,620 4470,550 4450,530 4200,530 4155,575 4155,1445 4235,1525 4325,1525 4360,1560 4360,1805 4555,2000 4905,2000 5025,2120 5025,2390 5010,2405 4855,2405 4830,2430 4830,2875 4855,2900 4980,2900 5005,2925 5005,3075 4980,3100 4900,3100 4875,3125 4875,3325 4900,3350 J50.2@5010,3350
NetJ15_L2: J15.L2 J50.1 | length 4090.8
  Signal Layer 7 w10: J15.L2@4510.16,704.96 4450,644.8 4450,565 4435,550 4210,550 4175,585 4175,1435 4245,1505 4335,1505 4380,1550 4380,1795 4565,1980 4915,1980 5045,2110 5045,2405 5025,2425 4880,2425 4850,2455 4850,2855 4875,2880 5015,2880 5025,2890 5025,3090 4960,3155 J50.1@4960,3250
NetJ15_L3: J15.L3 J50.6 | length 4517.8
  Signal Layer 7 w10: J15.L3@4560.16,754.96 4560.12,755 4480,755 4420,695 4420,610 4390,580 4245,580 4210,615 4210,1415 4270,1475 4360,1475 4410,1525 4410,1775 4560,1925 4940,1925 5100,2085 5100,2425 5070,2455 4910,2455 4885,2480 4885,2800 4910,2825 5035,2825 5075,2865 5075,3120 5015,3180 5015,3285 5060,3330 5060,3400 5085,3425 5190,3425 5210,3405 J50.6@5210,3350
NetJ15_L4: J15.L4 J50.3 | length 4052.2
  Signal Layer 7 w10: J15.L4@4510.16,804.96 4474.96,804.96 4400,730 4400,630 4370,600 4255,600 4230,625 4230,1405 4280,1455 4370,1455 4430,1515 4430,1760 4575,1905 4950,1905 5120,2075 5120,2440 5085,2475 4925,2475 4905,2495 4905,2785 4925,2805 5055,2805 5095,2845 5095,3145 5060,3180 J50.3@5060,3250
NetJ15_L5: J15.L5 J50.5 | length 3406.4
  Signal Layer 7 w10: J15.L5@4560.16,854.96 4560.12,855 4465,855 4420,900 4420,1460 4460,1500 4460,1745 4565,1850 4980,1850 5160,2030 5160,2450 5210,2500 5350,2500 5375,2525 5375,2725 5350,2750 5200,2750 5160,2790 J50.5@5160,3250
NetJ15_L6: J15.L6 J50.4 | length 3475.4
  Signal Layer 7 w10: J15.L6@4510.16,904.96 4465.04,904.96 4440,930 4440,1450 4480,1490 4480,1735 4575,1830 4990,1830 5180,2020 5180,2440 5220,2480 5360,2480 5395,2515 5395,2750 5375,2770 5215,2770 5180,2805 5180,3160 5210,3190 5210,3280 5190,3300 5160,3300 J50.4@5110,3350
NetJ15_L7: J15.L7 J50.8 | length 3458
  Signal Layer 7 w10: J15.L7@4560.16,954.96 4624.96,954.96 4645,975 4645,1400 4530,1515 4530,1715 4595,1780 5055,1780 5245,1970 5245,2385 5280,2420 5410,2420 5455,2465 5455,2825 5435,2845 5265,2845 5245,2865 5245,3110 5310,3175 J50.8@5310,3350
NetJ15_L8: J15.L8 J50.7 | length 3340.2
  Signal Layer 7 w10: J15.L8@4510.16,1004.96 4599.96,1004.96 4625,1030 4625,1390 4510,1505 4510,1725 4585,1800 5045,1800 5225,1980 5225,2430 5235,2440 5400,2440 5435,2475 5435,2805 5415,2825 5250,2825 5225,2850 5225,3125 5260,3160 J50.7@5260,3250
NetJ15_L15: J15.L15 J51.2 | length 2041.3
  Bottom Layer w10: J15.L15@4205.04,1599.84 4205.04,1855.04 4325,1975 5450,1975 5525,1900 5525,1600 5500,1575 J51.2@5450,1575
NetJ15_L18: J15.L18 J54.2 | length 1312.5
  Bottom Layer w10: J15.L18@4684.96,1599.84 J15.L18@4684.96,1599.84 4685,1910 4725,1950 5400,1950 5450,1900 J54.2@5450,1700
NetJ17_1: J17.1 R49.2 | length 93
  Bottom Layer w20: J17.1@800,325 R49.2@892.97,325
NetJ19_1: J19.1 R50.2 | length 93
  Bottom Layer w20: J19.1@800,825 R50.2@892.97,825
NetJ21_1: J21.1 R51.2 | length 93.5
  Bottom Layer w20: R51.2@5256.5,700 J21.1@5350,700
NetJ22_1: J22.1 R52.1 | length 93
  Bottom Layer w20: J22.1@800,450 R52.1@892.97,450
NetJ23_1: J23.1 R53.1 | length 93
  Bottom Layer w20: J23.1@800,950 R53.1@892.97,950
NetJ24_1: J24.1 R54.1 | length 93.5
  Bottom Layer w20: R54.1@5256.5,575 J24.1@5350,575
NetJ26_1: J26.1 R55.2 | length 93
  Bottom Layer w20: J26.1@800,1700 R55.2@892.97,1700
NetJ28_1: J28.1 R56.2 | length 93
  Bottom Layer w20: J28.1@800,1200 R56.2@892.97,1200
NetJ30_1: J30.1 R57.2 | length 93.5
  Bottom Layer w20: R57.2@5256.5,1325 J30.1@5350,1325
NetJ31_1: J31.1 R58.1 | length 93
  Bottom Layer w20: J31.1@800,1575 R58.1@892.97,1575
NetJ32_1: J32.1 R59.1 | length 93
  Bottom Layer w20: J32.1@800,1075 R59.1@892.97,1075
NetJ33_1: J33.1 R60.1 | length 93.5
  Bottom Layer w20: R60.1@5256.5,1450 J33.1@5350,1450
NetJ38_1: J38.1 R61.2 | length 93
  Bottom Layer w20: J38.1@800,575 R61.2@892.97,575
NetJ40_1: J40.1 R62.2 | length 93.5
  Bottom Layer w20: R62.2@5256.5,950 J40.1@5350,950
NetJ42_1: J42.1 R63.2 | length 93.5
  Bottom Layer w20: R63.2@5256.5,450 J42.1@5350,450
NetJ43_1: J43.1 R64.1 | length 93
  Bottom Layer w20: J43.1@800,700 R64.1@892.97,700
NetJ44_1: J44.1 R65.1 | length 93.5
  Bottom Layer w20: R65.1@5256.5,825 J44.1@5350,825
NetJ45_1: J45.1 R66.1 | length 93.5
  Bottom Layer w20: R66.1@5256.5,325 J45.1@5350,325
NetJ47_1: J47.1 R67.2 | length 93
  Bottom Layer w20: J47.1@800,1450 R67.2@892.97,1450
NetJ49_1: J49.1 R68.2 | length 93.5
  Bottom Layer w20: R68.2@5256.5,1075 J49.1@5350,1075
NetJ51_1: J51.1 R69.2 | length 93.5
  Bottom Layer w20: R69.2@5256.5,1575 J51.1@5350,1575
NetJ52_1: J52.1 R70.1 | length 93
  Bottom Layer w20: J52.1@800,1325 R70.1@892.97,1325
NetJ53_1: J53.1 R71.1 | length 93.5
  Bottom Layer w20: R71.1@5256.5,1200 J53.1@5350,1200
NetJ54_1: J54.1 R72.1 | length 93.5
  Bottom Layer w20: R72.1@5256.5,1700 J54.1@5350,1700
NetJ55_A1: J55.A1 J56.2 | length 2818.1
  Signal Layer 5 w10: J56.2@5835,2660 5735,2660 5700,2625 5700,2475 5725,2450 5790,2450 5850,2390 5850,1850 5900,1800 6175,1800 6200,1775 6200,685 6230,655 J55.A1@6509.92,654.96 J55.A1@6509.92,654.96
NetJ55_A2: J55.A2 J56.1 | length 2530.4
  Signal Layer 5 w10: J56.1@5785,2560 5785,2490 5870,2405 5870,1860 5910,1820 6190,1820 6220,1790 6220,720 6235.04,704.96 J55.A2@6559.92,704.96
NetJ55_A3: J55.A3 J56.6 | length 3012.9
  Signal Layer 5 w10: J56.6@6035,2660 6035,2705 6015,2725 5900,2725 5885,2710 5885,2635 5835,2585 5835,2495 5925,2405 5925,1900 5950,1875 6250,1875 6300,1825 6300,1750 6350,1700 6540,1700 6585,1655 6585,1560 6550,1525 6460,1525 6390,1455 6390,795 6430,755 J55.A3@6509.92,754.96 J55.A3@6509.92,754.96
NetJ55_A4: J55.A4 J56.3 | length 2606.1
  Signal Layer 5 w10: J56.3@5885,2560 5885,2480 5945,2420 5945,1915 5965,1895 6265,1895 6320,1840 6320,1760 6360,1720 6550,1720 6605,1665 6605,1550 6560,1505 6470,1505 6410,1445 6410,835 6440.04,804.96 J55.A4@6559.92,804.96
NetJ55_A5: J55.A5 J56.5 | length 2420.8
  Signal Layer 5 w10: J56.5@5985,2560 5985,2465 6000,2450 6000,1975 6025,1950 6320,1950 6375,1895 6375,1820 6420,1775 6565,1775 6635,1705 6635,1530 6580,1475 6495,1475 6440,1420 6440,875 6460.04,854.96 J55.A5@6509.92,854.96
NetJ55_A6: J55.A6 J56.4 | length 2562.9
  Signal Layer 5 w10: J56.4@5935,2660 5985,2610 6020,2610 6035,2595 6035,2525 6020,2510 6020,1990 6040,1970 6335,1970 6395,1910 6395,1830 6430,1795 6575,1795 6655,1715 6655,1524.72 6587.4,1457.13 6507.13,1457.13 6460,1410 6460,920 6475.04,904.96 J55.A6@6559.92,904.96
NetJ55_A7: J55.A7 J56.8 | length 2376.3
  Signal Layer 5 w10: J56.8@6135,2660 6135,2515 6075,2455 6075,2060 6090,2045 6395,2045 6455,1985 6455,1895 6480,1870 6605,1870 6705,1770 6705,1465 6645,1405 6645,1000 6599.96,954.96 J55.A7@6509.92,954.96
NetJ55_A8: J55.A8 J56.7 | length 2132.1
  Signal Layer 5 w10: J56.7@6085,2560 6085,2500 6055,2470 6055,2045 6075,2025 6380,2025 6435,1970 6435,1885 6470,1850 6595,1850 6685,1760 6685,1480 6625,1420 6625,1070.04 J55.A8@6559.92,1004.96
NetJ55_A15: J55.A15 J57.2 | length 969.9
  Signal Layer 5 w10: J57.2@5650,325 5650,250 5675,225 6130,225 6180,275 6180,350 6230,400 6347.17,400 J55.A15@6397.32,349.84
NetJ55_A18: J55.A18 J62.2 | length 1941.7
  Signal Layer 7 w10: J62.2@5650,450 5710,390 5800,390 5825,365 5825,150 5875,100 6950,100 7000,150 7000,350 6970.24,379.76 J55.A18@6912.28,379.76
NetJ55_B1: J55.B1 J65.2 | length 4940.5
  Signal Layer 7 w10: J65.2@5835,3355 5730,3355 5700,3325 5700,3150 5750,3100 5815,3100 5840,3075 5840,2940 5800,2900 5700,2900 5650,2850 5650,2455 5700,2405 5835,2405 5850,2390 5850,1850 5900,1800 6175,1800 6200,1775 6200,215 6240,175 6625,175 6700,250 6700,584.8 J55.B1@6770.16,654.96 J55.B1@6770.12,655
NetJ55_B2: J55.B2 J65.1 | length 4625.9
  Signal Layer 7 w10: J65.1@5785,3255 5785,3165 5860,3090 5860,2920 5820,2880 5720,2880 5670,2830 5670,2470 5715,2425 5850,2425 5870,2405 5870,1860 5910,1820 6190,1820 6220,1790 6220,230 6250,200 6624.72,200 6680,255.28 6680,664.8 J55.B2@6720.16,704.96
NetJ55_B3: J55.B3 J65.6 | length 4649.3
  Signal Layer 7 w10: J65.6@6035,3355 6035,3405 6015,3425 5905,3425 5885,3405 5885,3335 5835,3285 5835,3190 5925,3100 5925,2875 5875,2825 5730,2825 5705,2800 5705,2495 5725,2475 5855,2475 5925,2405 5925,1900 5950,1875 6250,1875 6300,1825 6300,1750 6350,1700 6540,1700 6585,1655 6585,1560 6550,1525 6460,1525 6390,1455 6390,615 6430,575 6630,575 6650,595 6650,725 6680,755 6770.12,755 J55.B3@6770.16,754.96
